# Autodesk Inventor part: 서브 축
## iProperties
Created: 2014-07
Part Number: 서브 축
Material: Steel
Document SubType Name: Modeling
Designer: KYOUNG IL JANG
Categories: <?xml version="1.0" encoding="UTF-16"?> <MemberInstance><Categories><FamilyTemplate><FamilyTemplateParameter ValueType="xs:double" Id="1" ObjectReferenceKey="da
Density: 1 g/cm^3
CustomPartVersion: 1
Company: 한국ATC센터
Author: KYOUNG IL JANG
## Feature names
1. Extrusion1
